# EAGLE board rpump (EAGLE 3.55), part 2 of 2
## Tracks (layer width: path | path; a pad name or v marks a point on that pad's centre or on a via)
+3,3V
  Top 0.305: 16.51,36.51 C38. | 16.51,36.51 16.51,36.49 | 26.67,23.81 26.67,24.13 28.26,25.72 | 30.16,27.64 28.26,27.64 28.26,27.62 | 28.26,25.72 28.26,27.62 | 28.26,25.72 SJ10. | 17.14,36.49 17.14,36.51 16.51,36.51 | 17.14,33.02 C31. | 20.57,36.49 20.64,36.49 | 20.64,37.29 20.57,37.29 | 27.47,33.59 27.47,31.6 26.99,31.11 26.99,28.26 27.62,27.62 28.26,27.62 | R49. 34.29,27.64 34.29,22.86
  Top 0.406: 17.14,36.49 20.57,36.49 | 20.64,36.49 20.64,37.29 | 46.99,29.21 48.26,27.94 48.26,26.04 48.9,25.4 50.8,25.4 IC8.
  Top 0.5: 17.14,36.51 17.14,33.02 17.14,26.04 19.37,23.81 26.67,23.81 27.62,22.86 34.29,22.86 39.37,22.86 40.64,21.59
  Top 0.61: 54.61,24.13 IC8. 49.53,21.59 40.64,21.59 40.64,15.24 | 46.99,29.21 44.45,29.21 | 67.31,27.94 66.04,29.21 62.23,29.21 | 40.64,15.24 41.27,15.24 | 40.64,15.24 40.64,13.97 38.1,11.43 | C36. 60.96,10.16 59.69,10.16 58.42,11.43 | 58.42,11.43 R54. | D1. 58.42,11.43
  Bottom 0.406: 52.07,46.99 53.34,45.72 53.34,40.64 54.61,39.37 53.98,38.73 53.98,29.21 55.88,27.3 55.88,25.4 | 54.61,24.13 55.88,25.4 | 62.23,29.21 60.96,27.94 60.96,26.04 60.33,25.4 55.88,25.4
  Bottom 0.61: IC8. 52.07,20.32 R27. D1. | 41.27,10.16 40.01,11.43 38.1,11.43
-5V
  Top 0.406: 120.91,14.92 121.61,14.92 122.56,13.97 125.73,13.97 125.73,14.1 126.87,14.1 130.18,10.79 135.25,10.79 142.24,3.81
/RES  (via drill 0.5 pad 1.02, 0.61 pad 1.27)
  Top 0.406: 132.08,82.55 132.08,81.28 | v97.79,64.77 90.17,64.77 88.9,66.04 | v92.71,34.29 88.9,30.48 72.39,30.48 68.58,26.67 64.77,26.67 63.5,27.94 58.42,27.94 57.15,26.67 | 148.59,68.58 150.5,70.48 150.5,84.14 149.54,85.09 135.89,85.09 | 135.89,85.09 134.62,85.09 132.08,82.55 | 136.43,89.33 135.89,88.79 135.89,85.09 | 104.14,83.82 v104.14,86.04 | 132.08,82.55 109.54,82.55 108.9,81.92 104.78,81.92 104.14,82.55 IC5. 104.14,83.82 | v101.6,83.82 104.14,83.82
  Bottom 0.406: 88.9,66.04 93.98,71.12 93.98,81.92 94.61,82.55 100.33,82.55 v101.6,83.82 | 96.52,38.1 97.79,39.37 | 96.52,38.1 94.61,38.1 93.98,38.73 93.98,50.8 97.79,54.61 v97.79,64.77 | 57.15,26.67 57.15,27.3 54.93,29.53 54.93,37.47 55.88,38.42 RN6. | 96.52,38.1 96.52,36.2 95.89,35.56 93.98,35.56 v92.71,34.29 | v104.14,86.04 104.14,88.27 SJ15.
AUX1L  (via drill 0.5 pad 1.02)
  Top 0.406: 24.13,83.82 20.32,80.01 16.51,80.01 X18. | 32.38,63.5 33.97,61.91 34.92,61.91 35.88,60.96 v37.47,60.96 | C21. v38.42,42.86
  Bottom 0.406: 13.97,84.58 13.97,85.09 X18. | 24.13,83.82 25.4,82.55 25.4,67.31 29.21,63.5 32.38,63.5 | v38.42,42.86 37.47,43.81 v37.47,60.96
AUX1R  (via drill 0.5 pad 1.02)
  Top 0.406: 11.43,77.47 13.97,74.93 27.94,74.93 29.21,76.2 | v33.66,67.31 33.66,64.77 34.92,63.5 36.51,61.91 v38.42,61.91 | 39.57,45.09 v38.42,45.09
  Bottom 0.406: v38.42,45.09 v38.42,61.91 | v33.66,67.31 29.21,71.75 29.21,76.2
AUX2L  (via drill 0.5 pad 1.02)
  Top 0.406: v38.42,38.42 C16. | v17.78,62.23 v17.78,69.85
  Bottom 0.406: v38.42,38.42 37.47,39.37 22.23,39.37 17.78,43.81 v17.78,62.23 | 21.59,83.82 17.78,80.01 v17.78,69.85 16.51,69.85 10.16,63.5 10.16,58.42 8.89,57.15 6.35,57.15 5.08,55.88
AUX2R  (via drill 0.5 pad 1.02)
  Top 0.406: v38.42,40.64 39.57,40.64 | v19.05,62.23 19.05,68.58 v20.32,69.85
  Bottom 0.406: v38.42,40.64 38.1,40.32 22.86,40.32 18.73,44.45 18.73,61.91 v19.05,62.23 | 21.59,76.2 21.59,71.12 v20.32,69.85 19.05,68.58 16.51,68.58 11.43,63.5 11.43,58.42 8.89,55.88 7.62,55.88
BUSY
  Bottom 0.406: 138.43,48.26 138.43,44.45 | 138.43,48.26 149.86,48.26 151.13,46.99 153.67,46.99 154.94,45.72 | 97.79,44.45 97.79,46.99 101.6,50.8 120.65,50.8 123.19,48.26 138.43,48.26
CLOCK  (via drill 0.5 pad 1.02)
  Top 0.406: 81.28,40.22 81.28,38.73 81.92,38.1 99.06,38.1 v100.33,36.83
  Bottom 0.406: v100.33,36.83 100.33,29.21
CTRL0
  Bottom 0.406: 152.4,25.4 146.05,25.4 137.79,25.4 137.16,24.77 137.16,22.86 138.43,21.59
CTRL1
  Bottom 0.406: 152.4,27.94 RN8. 137.16,27.94 135.89,26.67 135.89,21.59 138.43,19.05
D0
  Top 0.406: 105.41,26.67 105.41,25.4 107.95,22.86 127,22.86 R12. 129.54,22.86 143.51,22.86 144.78,21.59 147.32,21.59 148.59,22.86 152.4,22.86
  Bottom 0.406: 125.73,7.62 125.73,21.59 R12.
D1  (via drill 0.5 pad 1.02)
  Top 0.406: 105.41,29.21 106.68,27.94 106.68,25.4 107.95,24.13 v125.73,24.13
  Bottom 0.406: 125.73,5.08 124.46,6.35 124.46,22.86 v125.73,24.13 R13.
D2  (via drill 0.5 pad 1.02)
  Top 0.406: 107.95,26.67 109.22,25.4 v124.46,25.4
  Bottom 0.406: R14. v124.46,25.4 123.19,24.13 123.19,7.62
D3  (via drill 0.5 pad 1.02)
  Top 0.406: 107.95,29.21 109.22,27.94 121.92,27.94 v123.19,26.67
  Bottom 0.406: 123.19,5.08 121.92,6.35 121.92,25.4 v123.19,26.67 R15.
D4  (via drill 0.5 pad 1.02)
  Top 0.406: v120.65,26.67 110.49,26.67
  Bottom 0.406: R16. v120.65,26.67 120.65,7.62
D5  (via drill 0.5 pad 1.02)
  Top 0.406: v119.38,29.21 113.03,29.21
  Bottom 0.406: 120.65,5.08 119.38,6.35 v119.38,29.21 120.65,29.21 R17.
D6  (via drill 0.5 pad 1.02)
  Top 0.406: 110.49,29.21 111.76,30.48 v118.11,30.48
  Bottom 0.406: R18. 119.38,30.48 v118.11,30.48 118.11,7.62
D7  (via drill 0.5 pad 1.02)
  Top 0.406: v116.84,31.75 113.03,31.75
  Bottom 0.406: 118.11,5.08 116.84,6.35 v116.84,31.75 127,41.91 R19.
DCF  (via drill 0.5 pad 1.02)
  Top 0.406: 121.95,91.83 121.95,92.42 123.19,93.66 124.78,93.66 126.05,92.39 132.72,92.39 133.67,93.34 137.48,93.34 138.93,91.89 138.93,91.83 | 74.93,58.42 77.79,61.28 110.81,61.28 113.03,63.5 128.27,63.5 132.08,67.31 v144.78,67.31
  Bottom 0.406: 138.93,91.83 140.76,93.66 143.19,93.66 144.78,92.08 v144.78,67.31
DEMAND
  Top 0.406: 97.79,34.29 96.52,35.56 91.44,35.56 87.63,31.75 66.04,31.75 64.77,30.48 59.05,30.48 56.52,33.02 45.72,33.02 44.45,31.75
  Bottom 0.406: 50.16,63.5 50.48,63.5 52.07,61.91 52.07,60.33 51.12,59.37 50.16,59.37 44.45,53.66 44.45,41.91 45.72,40.64 45.72,33.02 44.45,31.75
DIG_IN  (via drill 0.5 pad 1.02)
  Top 0.406: v70.17,87.95 67.31,90.81 46.99,90.81 45.4,92.39 16.51,92.39 11.75,87.63 6.35,87.63 3.81,85.09 3.81,67.31 5.08,66.04
  Bottom 0.406: 77.47,60.33 77.47,62.23 78.74,63.5 78.74,68.58 76.2,71.12 76.2,78.74 72.39,82.55 72.39,85.72 v70.17,87.95
  Bottom 1.016: 77.47,60.33 77.47,58.42
DIG_OUT  (via drill 0.5 pad 1.02)
  Top 0.406: v84.45,57.15 v100.33,57.15 | v71.12,88.9 68.26,91.76 47.94,91.76 46.04,93.66 15.88,93.66 11.11,88.9 6.35,88.9 2.54,85.09 2.54,66.04 5.08,63.5
  Bottom 0.406: v100.33,57.15 100.33,62.23 101.6,63.5 101.6,66.04 | v84.45,57.15 84.45,69.22 77.47,76.2 77.47,78.74 73.66,82.55 73.66,86.36 v71.12,88.9
  Bottom 1.016: 101.6,66.04 101.6,67.94
DIGIGND
  Bottom 0.813: 77.47,91.44 79.25,91.44 | IC3. 66.04,87.63 69.85,91.44 77.47,91.44 | 77.64,88.33 77.64,91.44 77.47,91.44
DREH0
  Bottom 0.406: 91.44,7.62 92.71,8.89 92.71,16.51 93.98,17.78 93.98,22.86 95.25,24.13 97.79,24.13 99.06,25.4 99.06,38.1 101.6,40.64 101.6,43.18 102.87,44.45
DREH1
  Bottom 0.406: 93.98,5.08 95.25,6.35 95.25,16.51 96.52,17.78 96.52,22.54 97.16,23.18 99.38,23.18 101.6,25.4 101.6,39.37 102.87,40.64 102.87,41.91
GND  (via drill 0.5 pad 1.02, 0.61 pad 1.02, 0.61 pad 1.27, 0.81 pad 1.68, 1.3 pad 2.8)
  Top 0.305: 20.57,42.09 20.64,42.09 20.64,42.89 20.57,42.89 | 22.67,42.99 IC7. | 22.67,42.99 22.54,42.86 20.95,42.86 20.93,42.89 20.57,42.89 | C26. 30.8,58.1 v32.07,58.1 | C29. 22.54,58.1 v21.27,58.1 | 16.83,42.74 16.83,42.55 | 16.51,42.74 16.83,42.74 | 26.34,26.04 26.67,26.36 | v26.67,35.56 26.67,33.59 26.67,32.07 26.04,31.43 v26.04,27.3 26.04,26.04 26.34,26.04 | 22.67,42.99 22.73,42.99 v22.86,42.86 | 20.57,42.89 16.83,42.89 16.83,42.74 | 102.23,88.9 102.23,88.79 | C32. 22.53,25.09 22.86,24.77 26.04,24.77 26.34,25.07 26.34,26.04 | C28. 21.58,54.6 21.27,54.29 v21.27,53.98 | C25. 31.76,54.6 32.07,54.29 v32.07,53.98 | v33.02,48.58 33.97,48.58 33.97,47.94 | 32.96,25.72 32.96,24.7 32.38,24.13 v27.94,24.13 | 27.46,38.89 32.77,38.89
  Top 0.406: 125.73,12.38 SJ9. 125.73,12.7 123.66,12.7 123.66,13.02 | 21.91,13.65 21.91,13.66 23.81,13.66 23.81,13.65 22.86,13.65 22.86,11.43 | 78.74,5.08 80.01,6.35 92.71,6.35 93.98,7.62 | 104.14,91.44 104.14,88.9 | 104.14,88.9 104.14,89.1 | 104.14,88.9 102.23,88.9 | 115.57,16.51 107.95,16.51 106.68,17.78 102.87,17.78 100.33,15.24 | 85.09,44.45 81.28,44.45 80.01,43.18 80.01,40.22 80.01,37.15 | 78.74,34.07 78.74,36.51 79.38,37.15 80.01,37.15 | 85.09,34.07 v85.09,35.88 85.09,36.51 84.45,37.15 80.01,37.15 | 52.07,26.67 53.34,25.4 58.42,25.4 59.69,24.13 | 49.53,58.8 49.53,60.01 48.9,60.64 48.9,71.12 | v26.67,38.1 27.46,38.89 29.21,38.89 29.21,41.91 28.26,42.86 v22.86,42.86 | 100.33,81.28 99.06,80.01 96.52,80.01 95.25,81.28 | 104.14,91.44 JP1. | 104.14,91.44 104.57,91.44 | 103.15,96.18 104.14,95.19 104.14,91.44
  Top 0.5: 15.03,47.94 15.24,47.94 15.24,45.72 15.56,45.4 16.51,45.4 | 16.51,45.4 C24. | 16.51,42.74 16.51,42.86 16.51,45.4
  Top 0.61: 120.65,95.57 120.65,95.63 | 131.63,94.83 131.63,94.93 | 138.43,95.57 138.43,95.63 | 127.45,94.83 127.53,94.83 127.64,94.93 127.74,94.83 | 120.65,41.49 120.65,45.09 123.83,48.26 v123.83,49.53 | 93.98,7.62 97.79,7.62 X9. | 133.35,7.62 131.44,9.53 125.73,9.53 | 125.73,9.53 125.73,12.38 | 115.57,16.51 113.03,16.51 113.03,12.7 116.2,9.53 125.73,9.53 | U3. 44.45,26.67 | 57.15,41.91 54.61,41.91 | 13.97,33.02 15.25,33.02 | 78.74,5.08 77.15,3.49 68.9,3.49 66.04,6.35 | 16.51,42.86 15.56,41.91 14.61,41.91 | 13.97,41.91 14.61,41.91 | 14.61,41.91 14.61,46.99 | 60.96,13.97 62.23,12.7 | 62.23,12.7 63.5,12.7 66.04,10.16 66.04,6.35 | 62.23,12.7 62.23,12.06 | 66.04,6.35 63.5,6.35 | 11.43,39.37 9.53,41.27 9.53,45.4 10.48,46.35 10.48,58.1 7.62,60.96
  Top 0.7: 36.83,76.2 33.02,72.39 16.83,72.39 13.97,69.53 13.97,41.91
  Top 0.813: 113.85,94.83 114.59,95.57 120.65,95.57 127,95.57 127.64,94.93 | 145.23,94.83 144.49,95.57 138.43,95.57 132.37,95.57 131.63,94.83 127.74,94.83 | 152.4,48.26 152.4,45.72 150.81,44.13 150.81,42.23 152.4,40.64 152.4,38.1 152.4,35.56 152.4,33.02 152.4,30.48 | 132.08,73.66 134.62,73.66 137.16,73.66 139.7,76.2 148.59,76.2 | 82.55,24.13 80.01,24.13 78.42,25.72 73.98,25.72 72.39,24.13 71.12,22.86 67.31,22.86 | 67.31,43.18 66.04,44.45 57.15,44.45 | 48.9,71.12 R34. | 48.9,71.12 R33. | 43.18,6.35 42.55,6.99 38.1,6.99 | 38.1,6.99 38.1,6.35 | v12.7,81.28 15.24,78.74 16.51,78.74 | 13.97,39.37 11.43,39.37 | 13.97,39.37 13.97,33.02 13.97,31.75 11.43,29.21 | 13.97,39.37 13.97,41.91 | 16.51,78.74 16.51,77.47 | 26.67,78.74 16.51,78.74 | 26.67,78.74 26.67,76.2 | 31.75,78.74 26.67,78.74 | 31.75,78.74 31.75,83.82 31.75,88.27 | 36.83,78.74 31.75,78.74 | 36.83,76.2 36.83,78.74 | v123.83,49.53 123.83,56.52 125.73,58.42 128.27,58.42 | 36.83,78.74 v47.62,78.74 48.9,78.74 48.9,71.12 | 106.68,59.69 105.41,58.42 104.14,58.42 102.23,60.33 84.45,60.33 82.55,58.42 82.55,55.88 81.28,54.61 68.58,54.61 64.77,58.42 | 82.55,81.28 86.36,77.47 v92.71,77.47 v97.79,77.47 | 57.15,44.45 48.26,44.45 45.72,46.99 45.72,49.53 44.45,49.53 43.18,50.8 v39.69,50.8 | 57.15,44.45 57.15,46.99 | 38.1,6.99 18.1,6.99 X3. | 32.38,66.04 31.11,66.04 26.67,61.59 v26.67,60.01 | 128.27,58.42 135.57,58.42 G1. | 128.27,58.42 128.27,55.88 | v39.69,50.8 v39.69,52.07 | v39.69,49.53 v39.69,50.8 | 42.08,88.33 42.08,88.27 31.75,88.27 | 24.3,88.33 24.3,88.27 31.75,88.27
  Bottom 0.305: v27.94,24.13 26.04,26.04 v26.04,27.3
  Bottom 0.406: U3. 48.26,25.4 50.8,25.4 52.07,26.67 51.75,26.99 51.75,29.84 49.85,31.75 46.99,31.75 | 44.45,73.66 R5. R34. | R33. R4. 53.34,73.66 | v12.7,81.28 8.89,81.28 | v33.02,48.58 33.02,53.02 v32.07,53.98
  Bottom 0.61: 124.22,91.83 124.05,91.83 | 127.45,94.83 127.22,94.83 | 26.67,58.1 v21.27,58.1 | 26.67,58.1 v32.07,58.1 | 57.15,46.99 57.15,41.91 | 26.67,53.98 v21.27,53.98 21.27,50.16 20,48.9 20,45.72 v22.86,42.86 | 26.67,53.98 v32.07,53.98 | 26.67,57.15 26.67,53.98 | 26.67,57.15 26.67,58.1 | v26.67,60.01 26.67,57.15 | 42.23,63.5 42.55,63.5 | 85.09,73.66 87.63,73.66 90.17,73.66 92.71,73.66 v92.71,77.47 | 69.85,66.04 70.17,66.36
  Bottom 0.813: 127.22,94.83 124.22,91.83 127,89.05 127,83.82 127,81.28 127,78.74 | 133.35,7.62 134.62,7.62 142.24,15.24 | 93.98,7.62 93.98,15.24 | X9. 100.33,12.7 100.33,15.24 100.33,21.59 | 100.33,21.59 102.87,24.13 102.87,26.67 | 85.09,44.45 82.55,46.99 82.55,58.42 | 81.28,91.44 86.36,91.44 93.34,98.42 103.19,98.42 | 116.84,81.28 119.38,81.28 121.92,78.74 127,78.74 | 100.33,80.01 v97.79,77.47 97.79,73.66 101.6,69.85 105.41,69.85 108.58,66.67 108.58,61.59 106.68,59.69 106.68,58.42 110.49,54.61 121.92,54.61 125.73,58.42 121.92,62.23 119.38,62.23 115.57,66.04 115.57,68.58 | 100.33,80.01 102.87,80.01 | 100.33,80.01 100.33,81.28 | 127,78.74 132.08,73.66 | 82.55,24.13 82.55,33.34 v85.09,35.88 | v123.83,49.53 151.13,49.53 152.4,48.26 | 22.86,11.43 29.21,17.78 29.21,33.02 v26.67,35.56 v26.67,38.1 | 69.85,66.04 69.85,63.5 64.77,58.42 69.85,53.34 69.85,45.72 67.31,43.18 64.77,40.64 64.77,29.21 62.23,26.67 62.23,24.13 | 62.23,24.13 59.69,24.13 | 62.23,24.13 63.5,22.86 67.31,22.86 66.04,22.86 66.04,19.68 64.14,19.68 60.96,16.51 60.96,13.97 | 32.38,66.04 29.21,66.04 26.67,68.58 26.67,76.2 | 42.23,63.5 39.69,60.96 v39.69,52.07 v39.69,50.8 v39.69,49.53 39.69,48.9 40.32,48.26 40.32,35.88 39.37,34.92 39.37,17.78 36.2,14.61 36.2,8.26 38.1,6.35 | 148.59,76.2 X2. | 81.28,91.44 SJ13. | 70.17,66.36 70.17,70.8 66.04,74.93 59.86,81.11 59.86,88.33 59.86,86.36 54.46,86.36 52.11,88.71 | 100.33,21.59 97.79,21.59 | 7.62,68.58 7.62,66.04 7.62,63.5 7.62,60.96 | 11.43,29.21 11.43,19.37 X3. v5.4,16.51 | 113.85,94.83 110.25,98.42 103.19,98.42 | 81.28,91.44 83.82,91.44 83.82,86.36 82.55,85.09 | 81.28,83.82 82.55,85.09
  Bottom 0.813: 82.55,81.28 82.55,82.55 | 82.55,82.55 81.28,83.82 | 81.28,83.82 77.47,83.82 | 82.55,82.55 82.55,85.09 | 103.15,96.18 103.16,96.18 103.19,96.2 103.19,98.42
  pour Top (isolate 0.406): 121.92,43.81 125.73,43.81 125.73,52.7 121.92,52.7
I2CC  (via drill 0.5 pad 1.02)
  Top 0.406: 97.79,31.75 105.41,31.75 109.22,35.56 116.84,35.56 119.06,33.34 121.28,33.34 121.92,33.97 121.92,35.34 | v93.98,30.48 90.17,26.67 71.12,26.67 68.58,24.13 64.77,24.13 60.96,20.32 53.34,20.32 48.26,15.24 48.26,11.43 45.72,8.89 | 43.18,8.89 42.86,8.57 18.73,8.57 11.43,15.88 11.43,24.13 2.54,33.02 2.54,58.42 5.08,60.96
  Bottom 0.406: 97.79,31.75 96.52,30.48 v93.98,30.48 | 43.18,8.89 45.72,8.89
I2CD
  Top 0.406: 118.11,38.1 109.54,38.1 104.46,33.02 96.52,33.02 95.25,34.29 88.9,27.94 71.12,27.94 68.58,25.4 64.77,25.4 60.96,21.59 53.34,21.59 45.72,13.97 43.18,13.97 42.86,13.97 38.73,9.84 19.05,9.84 12.38,16.51 12.38,24.45 3.81,33.02 3.81,57.15 5.08,58.42 | 118.11,38.1 118.11,53.34 113.03,58.42 | IC17. 120.65,35.56 118.11,38.1
I_SEL0
  Top 0.406: 95.25,73.66 93.98,74.93 83.82,74.93 81.28,77.47 74.93,77.47 71.12,81.28 36.83,81.28 34.29,83.82
  Bottom 0.406: 96.52,58.42 96.52,62.23 95.25,63.5 95.25,73.66
I_SEL1  (via drill 0.5 pad 1.02)
  Top 0.406: 36.83,83.82 38.1,82.55 72.39,82.55 76.2,78.74 82.55,78.74 85.09,76.2 v96.52,76.2
  Bottom 0.406: 99.06,58.42 99.06,62.23 100.33,63.5 100.33,68.58 96.52,72.39 v96.52,76.2 96.52,80.01 97.79,81.28
INT
  Bottom 0.406: 154.94,43.18 153.67,44.45 151.13,44.45 148.59,46.99 143.51,46.99 142.24,45.72 RN4. 140.97,43.18 135.89,43.18 133.35,45.72 123.19,45.72 120.65,48.26 104.14,48.26 100.33,44.45
IR
  Top 0.406: 81.28,5.08 82.55,3.81 99.06,3.81 106.68,11.43
  Bottom 0.406: 106.68,11.43 109.22,13.97 109.22,34.92 109.86,35.56 111.76,35.56 113.03,36.83
KONTR
  Bottom 0.406: 92.71,29.21 95.25,29.21 | V3. 92.71,29.21 | 93.98,66.04 93.98,63.5 95.25,62.23 95.25,57.15 91.44,53.34 91.44,30.48 92.71,29.21
LCD_SEL  (via drill 0.5 pad 1.02)
  Top 0.406: v109.22,3.81 109.22,12.7 v106.68,15.24 | v106.68,38.1 106.68,39.69 105.73,40.64 101.6,40.64 100.33,41.91
  Bottom 0.406: 128.27,5.08 127,3.81 v109.22,3.81 | v106.68,15.24 v106.68,38.1
LED+
  Top 0.5: 115.57,7.62 116.84,6.35 116.84,3.81 118.11,2.54 144.78,2.54 146.37,4.13 146.37,8.57 143.51,11.43 140.97,11.43 135.89,16.51 128.27,16.51
LED-  (via drill 0.5 pad 1.02)
  Top 0.5: v21.59,3.81 23.5,1.91 41.27,1.91 V1. 45.09,1.91 112.39,1.91 X16.
  Bottom 0.5: 11.43,31.75 13.02,30.16 13.02,12.38 v21.59,3.81
LEFT  (via drill 0.5 pad 1.02)
  Top 0.406: v21.59,68.58 v29.21,68.58
  Bottom 0.406: 26.67,81.28 SJ2. | 26.67,81.28 26.67,83.82 26.67,86.17 36.83,96.33 | 26.67,81.28 26.67,78.74 27.94,77.47 27.94,69.85 v29.21,68.58 | v21.59,68.58 20.32,67.31 16.51,67.31 12.7,63.5 12.7,58.42 8.89,54.61 6.35,54.61 5.08,53.34
LIGHT
  Bottom 0.406: 110.49,31.75 111.76,30.48 111.76,11.43 102.87,2.54 59.69,2.54 55.88,6.35
MCL  (via drill 0.5 pad 1.02)
  Top 0.406: 77.47,34.07 77.47,34.29 v72.39,34.29 62.23,34.29 | 50.8,52.65 50.8,52.07 59.69,52.07 60.96,53.34 v72.39,53.34 | v57.47,30.48 51.44,30.48 v50.48,29.53
  Bottom 0.406: v72.39,34.29 v72.39,53.34 | 62.23,34.29 60.96,33.02 60.96,31.11 60.33,30.48 v57.47,30.48 | v50.48,29.53 49.85,29.53 48.26,27.94 46.35,27.94 45.72,27.3 45.72,25.4 44.45,24.13
MCL/4  (via drill 0.5 pad 1.02)
  Top 0.406: 81.28,34.07 v81.28,35.88 | v80.01,55.88 78.74,57.15 73.98,57.15 73.66,57.47 73.66,59.69 76.2,62.23 109.22,62.23 111.76,64.77 118.75,64.77 119.38,65.41 119.38,68.58 120.65,69.85 120.65,72.39 121.92,73.66
  Bottom 0.406: v81.28,35.88 80.01,37.15 v80.01,55.88
N$1
  Top 0.406: 139.7,73.66 137.16,71.12 RN1.
N$2
  Top 0.406: 95.25,21.59 96.52,20.32 106.68,20.32 107.95,19.05 R11.
N$3
  Bottom 0.406: 133.35,12.7 133.35,10.16 130.81,7.62
N$4
  Top 0.406: 41.27,5.08 44.45,5.08 R8.
N$5
  Bottom 0.406: R1. 44.45,17.78 44.45,13.34 43.81,12.7 39.37,12.7 V4.
N$6
  Bottom 0.61: 146.05,43.37 146.05,43.18 152.4,43.18
N$7
  Top 0.406: 48.26,52.65 48.26,52.55 | 48.26,52.65 | 48.26,58.8
  Top 0.5: 48.26,56.83 48.26,52.65 | 48.26,56.83 48.26,58.8 | C10. 46.67,56.83 48.26,56.83 | 48.26,52.55 48.26,49.53
  Bottom 0.61: 59.69,60.96 59.69,56.52 55.24,52.07 50.8,52.07 48.26,49.53
N$8
  Top 0.406: 46.99,58.8 | 46.99,58.8 46.99,60.96 | 46.99,58.8 46.09,58.8 43.18,55.88
N$9
  Top 0.406: IC19. | IC19. 50.8,60.96 | IC19. 50.8,56.83 51.75,55.88 54.61,55.88
N$10
  Bottom 0.406: R50. 88.9,91.44
N$11
  Top 0.406: 43.18,60.96 41.91,60.96 | 43.18,60.96 44.45,60.96 | 43.18,58.42 43.18,60.96
N$12  (via drill 0.5 pad 1.02)
  Top 0.406: v130.81,40.64 130.81,44.13 138.43,51.75 | 121.92,41.49 121.92,39.37 123.19,38.1 v125.09,38.1
  Bottom 0.406: v130.81,40.64 127.64,40.64 v125.09,38.1
N$13
  Top 0.406: 59.69,31.75 62.23,31.75
N$14
  Top 0.406: R52. 142.24,6.35 135.89,12.7
N$15
  Top 0.406: 54.61,60.96 53.34,60.96 | 54.61,60.96 55.88,60.96 | 54.61,58.42 54.61,60.96
N$16
  Top 0.61: 80.01,81.28 77.47,81.28 74.93,83.82
N$17
  Bottom 0.406: 36.2,5.08 39.05,5.08 41.59,7.62 43.81,7.62 44.45,6.99 44.45,5.08 R51.
N$18
  Top 0.406: IC6. 123.66,15.72 123.19,16.19 118.43,16.19 C15.
N$19
  Bottom 0.5: 11.43,41.91 14.29,39.05 14.29,13.34 24.13,3.49 37.78,3.49 V2.
N$20
  Top 0.406: 118.43,13.02 120.91,13.02 | 118.43,13.02 | 118.43,12.27 118.43,12.38 118.43,13.02
N$21
  Bottom 0.406: 114.3,81.28 118.11,77.47 123.19,77.47 125.73,74.93 125.73,72.39 127,71.12
N$22
  Top 0.305: C8. 107.95,91.44 107.95,89.1
N$23
  Bottom 0.61: SJ7. 8.89,82.55 11.43,82.55 13.97,82.55 SJ8.
N$24
  Top 0.406: 105.41,89.1 105.41,87.95 104.78,87.31 102.55,87.31 102.23,87 C9.
N$25
  Bottom 0.61: 8.89,79.76 8.89,80.01 11.43,80.01
N$26
  Top 0.406: 121.92,81.28 120.65,80.01 105.09,80.01 102.55,82.55 88.9,82.55 87.63,81.28
  Bottom 0.406: 87.12,78.74 87.63,78.74 87.63,81.28
N$27  (1 unrouted)
  Bottom 1.016: 80.01,58.42 80.01,60.33 | 117.25,89.33 117.16,89.33 117.16,87.63
N$28
  Top 0.406: 72.39,96.33 73.66,95.06 73.66,87.63 71.12,85.09
  Bottom 0.5: SJ12. 71.12,85.09
N$29
  Bottom 0.406: 116.84,71.12 114.3,73.66
N$30
  Bottom 0.406: 119.38,71.12 116.84,73.66
N$31
  Bottom 0.406: 121.92,71.12 119.38,73.66
N$32
  Top 0.406: 124.46,41.49 124.46,43.81 U4.
N$33
  Top 0.406: 137.16,81.28 133.35,77.47 130.81,77.47 128.27,74.93 128.27,72.39 129.54,71.12
N$34
  Top 0.406: 139.7,81.28 134.62,76.2 132.08,76.2 130.81,74.93 130.81,72.39 132.08,71.12
N$35
  Bottom 0.406: IC1. 116.84,76.2 121.92,76.2 123.19,74.93 123.19,72.39 124.46,71.12
N$36  (1 unrouted)
  Bottom 1.016: 99.06,66.04 99.06,67.94 | 124.05,89.33 124.14,89.33 124.14,87.63
N$37
  Bottom 0.406: 106.05,88.27 106.05,89.53 105.41,90.17 100.33,90.17 99.06,88.9
N$40
  Top 0.305: 36.63,38.42 36.2,38.42 34.12,40.49 32.77,40.49
N$42
  Top 0.61: 93.98,91.44 85.09,82.55 85.09,81.28
  Bottom 0.406: 85.09,78.74 SJ6. | 85.09,78.74 85.09,81.28 | 80.01,76.2 82.55,78.74 85.09,78.74
N$43
  Top 0.61: R7. R31.
  Bottom 0.5: 71.12,79.25 71.12,74.93 72.39,73.66 R7.
N$44
  Top 0.305: 36.63,42.86 36.2,42.86 35.42,42.09 32.77,42.09
N$45
  Top 0.305: C22. 36.2,40.64 35.55,41.29 32.77,41.29
N$46
  Top 0.305: C23. 36.2,45.09 34,42.89 32.77,42.89
N$47
  Top 0.305: 18.72,45.4 18.72,45.1 18.73,45.09 18.73,44.45 19.5,43.69 20.57,43.69
  Top 0.5: 18.72,45.4 18.73,45.4 18.73,47.94 C35.
N$48
  Top 0.305: R38. 28.26,29.53 28.27,29.53 28.27,33.59
N$49
  Top 0.305: R39. 30.16,29.84 29.07,30.94 29.07,33.59
N$50
  Top 0.305: R40. 32.07,29.84 31.11,30.8 30.48,30.8 29.87,31.41 29.87,33.59
N$56
  Top 0.305: 22.67,33.59 22.67,31.56 20.64,29.53 | 20.65,26.04 20.65,29.53 20.64,29.53 | 20.64,29.53 19.18,29.53 | 19.18,29.53 19.05,29.53 | R37. 19.38,29.53 19.18,29.53
N$57
  Top 0.305: 21.26,33.02 21.26,33.33 21.27,33.34 21.27,34.29 22.23,35.24 23.18,35.24 23.47,34.95 23.47,33.59 23.47,30.19 24.13,29.53 U1. 24.45,29.08 24.45,26.04 C33.
N$58
  Top 0.305: 28.26,49.23 28.26,49.21 28.27,49.21 28.27,45.79
N$59
  Top 0.305: R23. 28.26,52.72 28.26,52.7 30.8,52.7 30.8,52.72
N$60
  Top 0.305: R24. 28.26,56.21 28.56,56.21 28.57,56.2 28.59,56.21 30.8,56.21 32.05,56.21 32.38,55.88 32.38,55.24 32.7,54.93 33.66,54.93 33.66,54.62 33.66,54.61
N$61
  Top 0.305: R30. 25.08,49.21 25.07,49.21 25.07,45.79
N$62
  Top 0.305: 25.08,51.1 R32. 25.08,52.7 22.54,52.7 22.54,52.72
N$63
  Top 0.305: 25.08,54.6 R35. 22.55,56.21 22.54,56.2 | 22.54,56.2 22.54,55.88 21.27,55.88 20.95,55.56 20.95,55.24 20.65,54.94 20.65,54.93 19.68,54.93 R36. | 22.54,56.2 22.54,56.21
N$64
  Top 0.305: 28.27,60.33 28.27,60.64 28.26,60.64 R28. 28.26,58.1 27.3,58.1 26.99,57.78 26.99,48.26 27.47,47.78 27.47,45.79
N$65
  Top 0.305: C30. 25.07,58.1 25.08,58.1 | 25.08,58.1 25.08,58.09 | 25.08,58.1 26.04,58.1 26.35,57.78 26.35,50.48 26.04,50.16 24.13,50.16 23.81,49.85 23.81,47.94 24.27,47.48 24.27,45.79
N$66
  Top 0.305: 26.67,45.79 26.67,44.13 26.99,43.81 30.8,43.81 32.07,45.09 32.07,49.53 32.38,49.85 34.61,49.85 34.92,50.16 34.92,53.01 R41. 33.96,53.01 33.97,53.02 34.92,53.02 34.92,56.2 34.62,56.5 R29. 33.66,56.52 33.34,56.83 33.34,58.74 33.02,59.05 32.38,59.05 32.08,59.36 R43. C27.
N$67
  Top 0.305: 23.47,45.79 23.47,47.33 23.18,47.62 22.54,47.62 21.91,46.99 20.64,46.99 20.32,47.31 20.32,49.53 20,49.85 18.73,49.85 18.41,50.16 18.41,53.01 19.68,53.01 19.68,53.02 18.41,53.02 18.41,56.2 18.72,56.5 19.68,56.5 19.68,56.52 20,56.83 20,58.74 20.32,59.05 20.95,59.05 21.26,59.36 21.26,60.33 23.19,60.33
N$68
  Top 0.305: 30.67,49.21 30.8,49.21 30.8,49.23 | 30.67,45.79 30.67,49.21 | 30.67,49.21 31.11,49.21
N$69
  Top 0.305: C39. 33.66,51.1 33.66,51.13
N$70  (via drill 0.5 pad 1.02)
  Top 0.305: 29.87,45.79 29.87,47.6 v29.53,47.94 | C42. 21.6,49.23 21.27,48.9 v21.27,47.94
  Bottom 0.305: v21.27,47.94 v29.53,47.94
N$71
  Top 0.305: R42. 19.68,51.12 19.7,51.1 22.54,51.1
N$72
  Top 0.305: 31.43,25.72 31.75,25.72 31.75,27.64 32.07,27.64
N$73
  Top 0.305: 33.96,60.33 34.29,60.33 34.29,58.1 37.47,54.93 C46.
N$74
  Top 0.305: R44. 19.05,59.99 19.05,58.1 16.19,55.24 15.88,55.24 C47.
N$77
  Top 0.406: 90.17,81.28 92.71,78.74 132.08,78.74 133.35,80.01 133.35,82.55 134.62,83.82 148.59,83.82
N$78  (via drill 0.5 pad 1.02)
  Top 0.305: 20.57,40.49 17.63,40.49 v16.51,39.37
  Top 0.406: C43. 16.51,20.32 v16.51,20.95
  Bottom 0.406: v16.51,20.95 v16.51,39.37
N$80  (via drill 0.5 pad 1.02)
  Top 0.305: 20.57,38.89 18.58,38.89 v18.1,39.37
  Top 0.406: C44. 29.17,21.91 v17.46,21.91
  Bottom 0.406: v18.1,39.37 17.46,38.73 v17.46,21.91
N$81
  Top 0.305: 19.96,20.32 20,20.28 20,15.54
  Top 0.406: 20,15.54 R45.
N$82
  Top 0.305: 25.76,20.32 25.72,20.28 25.72,15.54
  Top 0.406: 25.72,15.54 R46. 23.81,15.56
N$83  (via drill 0.5 pad 1.02)
  Top 0.305: 33.97,45.09 C45. 33.97,45.72 v34.92,45.72 | 33.97,29.52 v33.97,32.38 | 32.77,38.09 34.61,38.09 v34.61,38.1
  Bottom 0.305: v33.97,32.38 34.61,33.02 34.61,37.15 | 34.61,37.15 v34.61,38.1 | v34.92,45.72 34.92,44.13 37.15,41.91 38.73,41.91 39.37,41.27 39.37,37.78 38.73,37.15 34.61,37.15
N$87
  Bottom 0.406: 114.3,71.12 111.76,73.66
N$90  (via drill 0.5 pad 1.02)
  Top 0.406: v92.71,67.31 111.76,67.31 113.03,66.04
  Bottom 0.406: 93.98,58.42 93.98,62.23 92.71,63.5 v92.71,67.31
N$98
  Top 0.406: 123.19,41.49 123.19,43.81 122.56,44.45
OUT_L
  Top 0.406: R2. 42.55,70.48 42.55,66.04 41.27,64.77 41.27,62.55 37.47,58.74 37.47,58.47
  Bottom 0.406: 41.91,73.66 R2. 31.75,71.12 30.48,72.39 30.48,77.47 29.21,78.74 29.21,81.28 | 29.21,81.28 29.21,83.82 | 29.21,81.28 28.7,81.28
OUT_R  (via drill 0.5 pad 1.02)
  Top 0.406: 15.88,58.47 15.88,69.85 17.14,71.12 v19.05,71.12 34.92,71.12 40.01,66.04
  Bottom 0.406: 55.88,73.66 R3. 54.61,69.85 43.81,69.85 40.01,66.04 | 20.83,78.74 20.32,78.23 20.32,77.47 19.05,76.2 v19.05,71.12
PD0
  Bottom 0.406: 154.94,22.86 153.67,24.13 142.24,24.13 138.43,24.13
PD1
  Bottom 0.406: 154.94,25.4 153.67,26.67 142.24,26.67 138.43,26.67
PD2
  Bottom 0.406: 154.94,27.94 153.67,29.21 142.24,29.21 138.43,29.21
PD3
  Bottom 0.406: 154.94,30.48 153.67,31.75 142.24,31.75 138.43,31.75
PD4
  Bottom 0.406: 154.94,33.02 153.67,34.29 142.24,34.29 138.43,34.29
PD5
  Bottom 0.406: 138.43,36.83 142.24,36.83 153.67,36.83 154.94,35.56
PD6
  Bottom 0.406: 138.43,39.37 142.24,39.37 153.67,39.37 154.94,38.1
PD7
  Bottom 0.406: 138.43,41.91 142.24,41.91 153.67,41.91 154.94,40.64
PH_L
  Top 0.406: R47. 20.32,13.66 X1.
  Bottom 0.406: 34.92,66.04 33.66,64.77 33.66,62.55 33.34,62.23 28.89,62.23 26.67,64.45 16.83,64.45 15.24,62.87 15.24,16.51 X1.
PH_R
  Top 0.406: R48. 25.4,13.66 25.4,11.43
  Bottom 0.406: 37.47,66.04 36.2,64.77 36.2,62.55 34.92,61.28 28.26,61.28 26.04,63.5 17.46,63.5 16.51,62.55 16.51,43.18 21.59,38.1 21.59,10.48 21.91,10.16 24.13,10.16 25.4,11.43
PI0
  Top 0.406: RN7. 60.96,33.02 59.69,34.29
PI1
  Bottom 0.406: 63.5,49.53 63.5,38.1 62.23,36.83
PI2
  Top 0.406: 67.31,35.56 60.96,35.56 59.69,36.83
PI3
  Top 0.406: 67.31,38.1 66.04,39.37 62.23,39.37
PI4
  Top 0.406: 67.31,40.64 60.96,40.64 59.69,41.91
PI8  (via drill 0.5 pad 1.02)
  Top 0.406: 52.07,41.91 53.34,40.64 53.34,36.2 v52.7,35.56
  Bottom 0.406: v52.7,35.56 52.7,28.26 53.34,27.62 53.34,21.59 55.88,19.05
RES_MAN  (via drill 0.5 pad 1.02)
  Top 0.305: 109.86,87 109.86,86.88
  Top 0.406: 107.67,96.18 106.05,94.55 106.05,90.49 106.68,89.85 106.68,89.1 106.68,87.63 107.31,87 | 107.31,87 109.86,87 | v107.31,86.68 107.31,87
  Bottom 0.406: 107.57,88.27 107.63,88.27 107.31,87.95 v107.31,86.68
RIGHT
  Bottom 0.406: 22.86,78.74 22.86,85.09 21.59,86.36 21.59,93.79 19.05,96.33 | 22.86,78.74 SJ4. | 22.86,78.74 22.86,77.47 24.13,76.2 24.13,68.58 21.59,66.04 16.51,66.04 13.97,63.5 13.97,58.42 8.89,53.34 SV1.
ROW3
  Top 0.406: 76.2,5.08 74.93,6.35 74.93,11.43 80.01,16.51
ROW4
  Top 0.406: 73.66,7.62 73.66,11.43 77.47,15.24 77.47,16.51
ROW5
  Top 0.406: 73.66,5.08 72.39,6.35 72.39,11.43 74.93,13.97 74.93,16.51
ROW6
  Top 0.406: 71.12,7.62 71.12,11.43 72.39,12.7 72.39,16.51
ROW7  (via drill 0.5 pad 1.02)
  Top 0.406: X17. 69.85,6.35 69.85,19.05 74.93,24.13 | v74.93,55.88 69.85,55.88 67.31,58.42
  Bottom 0.406: 74.93,24.13 v74.93,55.88
RX  (via drill 0.5 pad 1.02)
  Top 0.406: v96.52,55.88 110.49,55.88 v111.76,57.15
  Bottom 0.406: 95.25,36.83 93.98,36.83 92.71,38.1 92.71,52.07 v96.52,55.88 | v111.76,57.15 121.92,57.15 123.19,58.42
RXD  (via drill 0.5 pad 1.02)
  Top 0.406: 120.65,58.42 121.92,59.69 v134.94,59.69
  Bottom 0.406: v134.94,59.69 134.94,62.87 138.43,66.36 138.43,89.33
SCHALT2  (via drill 0.5 pad 1.02)
  Top 0.406: v116.84,45.72 v107.95,54.61
  Bottom 0.406: 104.14,66.04 102.87,64.77 102.87,57.15 105.41,54.61 v107.95,54.61 | v116.84,45.72 115.57,44.45 115.57,35.56 114.3,34.29 114.3,25.4 113.03,24.13 113.03,11.43 102.87,1.27 58.42,1.27 55.88,3.81
SCL3  (via drill 0.5 pad 1.02)
  Top 0.305: 25.07,33.59 25.07,34.91 25.08,34.92 25.08,36.51 25.72,37.15 29.21,37.15 31.75,34.61 33.34,34.61 35.24,32.7 v42.55,32.7
  Top 0.406: 57.15,24.13 55.88,22.86 53.34,22.86 50.8,20.32 v46.99,20.32
  Bottom 0.406: V6. 45.72,11.43 46.99,12.7 v46.99,20.32 45.72,21.59 44.13,21.59 42.55,23.18 v42.55,32.7 42.55,48.9 41.91,49.53 41.91,56.52 42.55,57.15 45.4,57.15 48.9,60.64 48.9,64.77 47.62,66.04
SCLK  (via drill 0.5 pad 1.02)
  Top 0.406: 95.25,39.37 93.03,39.37 86.68,45.72 73.66,45.72 68.58,50.8 62.23,50.8 60.96,49.53 | v135.89,68.58 146.05,68.58 148.59,66.04
  Bottom 0.406: 59.69,39.37 60.96,40.64 60.96,49.53 60.96,61.91 55.56,67.31 46.35,67.31 45.09,66.04 | 95.25,39.37 96.52,40.64 96.52,43.18 95.25,44.45 95.25,49.53 99.06,53.34 123.19,53.34 135.89,66.04 v135.89,68.58 135.89,82.23 134.62,83.5 | 134.43,89.33 134.62,89.14 134.62,84.45
  Bottom 1.016: 134.62,83.5 134.62,84.45
SDA3  (via drill 0.5 pad 1.02)
  Top 0.305: 25.87,33.59 25.87,34.77 25.72,34.92 25.72,36.2 26.04,36.51 27.94,36.51 v28.57,35.88
  Top 0.406: V5. 45.72,16.51 | v36.2,30.48 v41.59,30.48 47.94,30.48 50.48,27.94 53.34,27.94 54.61,26.67
  Bottom 0.406: 47.62,63.5 47.31,63.5 45.72,61.91 45.72,60.33 45.09,59.69 42.23,59.69 40.96,58.42 40.96,49.21 41.59,48.58 v41.59,30.48 41.59,18.1 V5. | v28.57,35.88 33.97,30.48 v36.2,30.48
SDATA  (via drill 0.5 pad 1.02)
  Top 0.406: 58.42,49.53 60.96,52.07 v61.91,52.07 69.85,52.07 74.93,46.99 87.31,46.99 88.58,45.72 95.25,45.72 | 95.25,45.72 v96.52,45.72 | 95.25,45.72 95.25,41.91 | v142.24,71.12 148.59,71.12
  Bottom 0.406: 57.15,39.37 58.42,40.64 58.42,49.53 | 142.43,89.33 142.24,89.14 v142.24,71.12 142.24,61.59 135.25,54.61 127,54.61 124.46,52.07 100.33,52.07 96.52,48.26 v96.52,45.72 | 45.09,63.5 43.81,64.77 43.81,67.31 45.09,68.58 55.88,68.58 61.91,62.55 v61.91,52.07
SEL0
  Top 0.406: R26. 107.95,21.59 104.14,25.4 99.06,25.4 97.79,26.67
  Bottom 0.406: R26. 127,20.32 127,8.89 128.27,7.62
SEL1
  Top 0.406: R25. 127,20.32 107.95,20.32 104.14,24.13 97.79,24.13 96.52,25.4 96.52,27.94 97.79,29.21
  Bottom 0.406: R25. 129.54,17.78 129.54,6.35 130.81,5.08
SOC  (via drill 0.5 pad 1.02)
  Top 0.305: 32.77,35.69 33.84,35.69 34.61,34.92 41.27,34.92 41.91,35.56
  Top 0.406: 124.46,73.66 123.19,74.93 107.95,74.93 102.87,69.85 X21. 62.87,64.14 62.87,57.47 v58.74,53.34 | 41.91,35.56 50.8,35.56 52.07,36.83 52.07,39.37
  Bottom 0.406: 52.07,39.37 50.8,40.64 50.8,49.53 52.07,50.8 56.2,50.8 v58.74,53.34
SOD  (via drill 0.5 pad 1.02)
  Top 0.305: 32.77,36.49 34,36.49 34.61,35.88 40.96,35.88 43.18,38.1
  Top 0.406: v127,76.2 125.73,77.47 107.95,77.47 102.87,72.39 66.04,72.39 63.5,69.85 58.42,64.77 v58.42,59.69 | 43.18,38.1 48.26,38.1 49.53,39.37 | 46.99,52.65 | v46.99,50.8 46.99,52.65
  Bottom 0.406: v127,76.2 129.54,73.66 | 49.53,39.37 48.26,40.64 48.26,46.99 46.99,48.26 v46.99,50.8 49.53,53.34 54.61,53.34 58.42,57.15 v58.42,59.69
SOI  (via drill 0.5 pad 1.02)
  Top 0.305: 32.77,37.29 34.15,37.29 34.61,36.83 40.64,36.83 41.27,37.47 41.27,39.37
  Top 0.406: 49.53,52.65 | v49.53,46.99 49.53,52.65 | 127,73.66 124.46,76.2 107.95,76.2 102.87,71.12 67.31,71.12 66.04,69.85 61.59,65.41 61.59,59.05 57.15,54.61 50.16,54.61 49.53,53.98 49.53,52.65 | 49.53,41.91 48.26,40.64 42.55,40.64 41.27,39.37
  Bottom 0.406: 49.53,41.91 v49.53,46.99
SONY  (via drill 0.5 pad 1.02)
  Top 0.406: v73.66,68.58 104.14,68.58 105.41,69.85 111.76,69.85 114.3,67.31 116.84,67.31 118.11,66.04
  Bottom 0.406: 72.39,58.42 72.39,62.23 73.66,63.5 v73.66,68.58 73.66,69.85 63.5,80.01 63.5,90.17 57.61,96.06 57.61,96.21 54.61,96.21 | 54.61,96.21 51.61,96.21 | 54.61,96.52 54.61,96.33 54.61,96.21
SPDIFAUX  (via drill 0.5 pad 1.02)
  Top 0.406: v85.09,85.09 73.66,85.09 72.39,83.82 52.07,83.82 44.77,91.12 17.14,91.12 12.38,86.36 6.35,86.36 5.08,85.09 5.08,68.58
  Bottom 0.406: 92.71,81.28 91.44,82.55 87.63,82.55 v85.09,85.09
SREAD  (via drill 0.5 pad 1.02)
  Top 0.406: 146.05,22.86 143.51,25.4 143.51,45.72 142.24,46.99 | v136.84,46.99 142.24,46.99 | 142.24,46.99 142.24,63.5 v140.97,64.77 | v140.97,72.39 142.24,73.66 148.59,73.66
  Bottom 0.406: 152.4,20.32 148.59,20.32 146.05,22.86 | 97.79,41.91 99.06,43.18 99.06,45.72 102.87,49.53 120.65,49.53 123.19,46.99 v136.84,46.99 | v140.97,64.77 v140.97,72.39 140.97,83.19 140.65,83.5 | 140.43,89.33 140.65,89.11 140.65,84.45
  Bottom 1.016: 140.65,83.5 140.65,84.45
STROBE  (via drill 0.5 pad 1.02)
  Top 0.406: 142.24,17.78 144.78,20.32 146.05,20.32 | 95.25,31.75 96.52,30.48 106.68,30.48 109.22,33.02 117.47,33.02 120.02,30.48 v133.35,30.48
  Bottom 0.406: 154.94,20.32 153.67,19.05 147.32,19.05 146.05,20.32 | v133.35,30.48 133.35,21.59 137.16,17.78 142.24,17.78
T4/R0
  Bottom 0.406: 86.36,7.62 86.36,12.7 82.55,16.51 83.82,17.78 SJ1.
T5/R1
  Bottom 0.406: 88.9,5.08 87.63,6.35 87.63,13.97 85.09,16.51 86.36,17.78 SJ3.
T6/R2
  Bottom 0.406: 88.9,7.62 88.9,15.24 87.63,16.51 88.9,17.78 SJ5.
TAKT  (via drill 0.5 pad 1.02)
  Top 0.305: 24.27,33.59 24.27,38.24 v27.62,41.59
  Top 0.406: 77.47,44.45 78.74,43.18 78.74,40.22 78.74,37.78 77.79,36.83 64.77,36.83 63.5,38.1 v58.42,38.1 58.42,43.18 45.72,43.18 41.91,46.99 v35.56,46.99
  Bottom 0.406: 59.69,26.67 55.88,30.48 55.88,35.56 v58.42,38.1 | v27.62,41.59 33.02,46.99 v35.56,46.99 35.56,60.64 37.47,62.55 37.47,63.5
TAST0  (via drill 0.5 pad 1.02)
  Top 0.406: 107.95,41.91 106.68,43.18 106.68,45.72 105.41,46.99 89.22,46.99 87.95,48.26 76.2,48.26 v73.66,50.8
  Bottom 0.406: 81.28,7.62 73.66,15.24 v73.66,50.8 73.66,62.23 74.93,63.5 74.93,66.04
TAST1  (via drill 0.5 pad 1.02)
  Top 0.406: 107.95,44.45 107.95,45.72 105.41,48.26 89.85,48.26 88.58,49.53 77.47,49.53 v76.2,50.8
  Bottom 0.406: 83.82,5.08 82.55,6.35 82.55,8.89 76.2,15.24 v76.2,50.8 76.2,62.23 77.47,63.5 77.47,66.04
TAST2  (via drill 0.5 pad 1.02)
  Top 0.406: 110.49,41.91 109.22,43.18 109.22,45.72 105.41,49.53 90.49,49.53 89.22,50.8 v78.74,50.8
  Bottom 0.406: 83.82,7.62 83.82,10.16 78.74,15.24 v78.74,50.8 78.74,62.23 80.01,63.5 80.01,66.04
TAST3  (via drill 0.5 pad 1.02)
  Top 0.406: 110.49,44.45 110.49,45.72 105.41,50.8 91.44,50.8 90.17,52.07 v81.28,52.07
  Bottom 0.406: 86.36,5.08 85.09,6.35 85.09,11.43 81.28,15.24 81.28,33.97 82.55,35.24 82.55,36.51 81.28,37.78 v81.28,52.07 81.28,62.23 82.55,63.5 82.55,66.04
TAST4  (via drill 0.5 pad 1.02)
  Top 0.406: 113.03,41.91 113.03,44.45 105.41,52.07 92.39,52.07 91.12,53.34 v86.36,53.34
  Bottom 0.406: 83.82,21.08 83.82,22.86 85.09,24.13 86.36,25.4 v86.36,53.34 86.36,58.42
TAST5  (via drill 0.5 pad 1.02)
  Top 0.406: 110.49,39.37 111.76,40.64 113.67,40.64 114.3,41.27 114.3,44.45 105.41,53.34 93.34,53.34 92.08,54.61 v87.63,54.61
  Bottom 0.406: 86.36,21.08 86.36,22.86 87.63,24.13 v87.63,54.61 87.63,57.15 88.9,58.42
TAST6  (via drill 0.5 pad 1.02)
  Top 0.406: 113.03,39.37 113.67,39.37 115.57,41.27 115.57,44.45 105.41,54.61 94.3,54.61 93.03,55.88 v88.9,55.88
  Bottom 0.406: 88.9,21.08 88.9,22.86 90.17,24.13 88.9,25.4 v88.9,55.88 91.44,58.42
TAST7  (via drill 0.5 pad 1.02)
  Top 0.406: v105.41,39.37 100.33,39.37 99.06,40.64 93.34,40.64 v90.17,43.81
  Bottom 0.406: 91.44,5.08 90.17,6.35 90.17,8.89 91.44,10.16 91.44,28.89 90.17,30.16 v90.17,43.81 90.17,54.61 92.71,57.15 92.71,62.23 91.44,63.5 91.44,66.04 | 110.49,36.83 107.95,39.37 v105.41,39.37
TRANSMIT  (via drill 0.5 pad 1.02)
  Top 0.406: 101.6,58.42 102.87,57.15 109.22,57.15 110.49,58.42 114.3,62.23 129.54,62.23 v133.35,66.04
  Bottom 0.406: 134.43,91.83 130.81,88.21 130.81,77.47 133.35,74.93 v133.35,66.04
TXD  (via drill 0.5 pad 1.02)
  Top 0.406: 115.57,58.42 118.11,60.96 130.81,60.96 135.89,66.04 v143.51,66.04
  Bottom 0.406: 142.43,91.83 143.83,90.43 143.83,87.95 143.51,87.63 v143.51,66.04
VCC  (via drill 0.5 pad 1.02, 0.61 pad 1.27, 0.81 pad 1.68, 1.3 pad 2.8)
  Top 0.305: 106.68,83.82 106.68,83.62 | 109.86,83.82 109.86,83.93 | 107.95,83.82 107.95,83.62
  Top 0.406: 106.68,83.82 107.95,83.82 109.86,83.82 v111.76,83.82 | R10. 120.91,13.97
  Top 0.61: v77.47,41.91 77.47,40.22 v77.47,38.42 | 124.46,35.34 125.2,35.34 126.36,36.51 126.36,42.55 R53. | 7.62,58.42 9.21,56.83 9.21,46.99 8.26,46.04 8.26,37.47 X7.
  Top 0.7: 31.75,76.2 29.21,73.66 v13.97,73.66
  Top 0.813: 77.47,24.13 82.55,19.05 90.17,19.05 | 90.17,19.05 IC11. 86.36,12.7 81.28,12.7 76.2,7.62 | 90.17,19.05 R9. | 91.44,91.44 86.36,86.36 81.28,86.36 | 142.24,21.59 140.97,20.32 140.97,19.05 R6. | R53. v128.27,50.8 | v13.97,73.66 12.06,71.75 12.06,45.09 X8. | 64.77,63.5 67.31,63.5 | 67.31,63.5 86.36,63.5 | 86.36,63.5 IC12. | 67.31,63.5 IC13. | 86.36,63.5 106.68,63.5 | 106.68,63.5 106.68,64.77 | IC18. 107.95,63.5 106.68,63.5 | X15. v147.32,45.72 | 50.16,66.04 54.61,66.04 L1. | 118.11,58.42 119.38,57.15 v119.38,46.99 | 66.04,49.53 73.66,41.91 v77.47,41.91
  Bottom 0.406: R10. 114.3,15.24 114.3,22.86 115.57,24.13 115.57,33.02 116.84,34.29 116.84,40.01 119.38,42.55 | 102.87,21.59 104.14,22.86 104.14,43.18 IC9.
  Bottom 0.61: 146.05,17.78 146.05,12.7 142.24,8.89 138.43,5.08 133.35,5.08 | 117.25,91.67 117.25,91.83 | SJ14. 146.49,44.9 v147.32,45.72 | 58.42,8.89 58.42,8.57
  Bottom 0.813: 117.25,91.83 116.52,92.56 116.52,96.84 117.79,98.11 132.4,98.11 134.62,95.89 134.62,94.14 136.93,91.83 | 142.24,21.59 146.05,17.78 154.94,17.78 156.84,19.68 156.84,51.75 156.21,52.39 152.4,52.39 | v77.47,41.91 U2. 77.47,24.13 | 102.87,73.66 IC15. | 91.44,91.44 99.06,83.82 100.65,85.41 102.55,85.41 104.14,83.82 109.22,83.82 | 102.87,73.66 102.87,74.93 | 109.22,73.66 102.87,73.66 | 109.22,73.66 111.76,71.12 111.76,69.85 110.49,68.58 IC18. 118.11,58.42 | 121.92,83.82 124.46,81.28 | 117.25,91.67 121.92,87 121.92,83.82 | 121.92,83.82 v111.76,83.82 109.22,83.82 | 109.22,73.66 109.22,83.82 | 152.4,52.39 150.81,52.39 148.59,54.61 | 66.04,11.43 72.39,11.43 76.2,7.62 | IC14. 17.78,82.55 16.51,82.55 16.51,80.33 13.97,77.79 v13.97,73.66 | R53. 127.64,44.45 125.73,42.55 119.38,42.55 v119.38,46.99 107.95,46.99 IC9. | 8.57,34.29 X7. | 8.57,34.29 8.57,41.59 X8. | 152.4,52.39 X15. | 66.04,49.53 66.04,54.61 63.18,57.47 63.18,61.91 64.77,63.5 | 148.59,54.61 X14. | 31.75,76.2 34.29,73.66 38.1,73.66 40.64,76.2 52.7,76.2 | 52.7,76.2 55.88,76.2 59.69,72.39 L1. | 52.7,76.2 v52.7,78.74 51.44,78.74 | v128.27,50.8 128.27,53.34 136.21,53.34 137.48,54.61 148.59,54.61 | R56. 58.42,11.43 58.42,8.89 R55. 48.9,1.91 20.32,1.91 9.53,12.7 4.76,12.7 2.22,15.24 2.22,18.41 v5.4,21.59 8.57,21.59 8.57,34.29 | 58.42,6.35 58.42,8.57 61.91,8.57 IC10. 64.77,10.16 66.04,11.43 | 66.04,17.14 66.04,13.97 66.04,11.43
VCONTR
  Top 0.406: SJ11. 129.86,12.7 124.78,17.78 107.95,17.78 106.68,19.05 105.41,19.05
  Bottom 0.406: 105.41,19.05 R20. 105.41,15.24 | 105.41,15.24 105.41,13.97 | 102.87,15.24 105.41,15.24
VIR
  Top 0.406: 102.87,19.05 100.33,19.05 96.52,15.24
  Bottom 0.406: 78.74,7.62 80.01,6.35 80.01,4.45 80.64,3.81 96.52,3.81 101.6,8.89 | 101.6,8.89 101.92,9.21 | 101.92,9.21 104.14,11.43 | 96.52,15.24 96.52,13.97 101.28,9.21 | 101.6,8.89 101.28,9.21 | 101.92,9.21 101.28,9.21

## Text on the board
Top: RPump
